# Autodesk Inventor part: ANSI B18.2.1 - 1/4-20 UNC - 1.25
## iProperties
Comments: To add or edit properties for Autodesk Inventor files, use iProperties.
Created: 2004-12
Part Number: ANSI B18.2.1 - 1/4-20 UNC - 1.25
Vendor: Autodesk Inc.
Document SubType Name: Modeling
Designer: John Blackburn
Material: Default
Description: Hex Cap Screw
Standard: ANSI B18.2.1
Alert: To add or edit properties for Autodesk Inventor files, use iProperties.
Control State: 0
Master: False
Checked Out: False
Shininess: 64.0
Length Units: 11272
Angle Units: 11279
Time Units: 11290
Mass Units: 11286
Length Display Precision: 3
Angle Display Precision: 2
Compacted: True
EGR: 3
Classification: un/spsc 31161513
Density: 0.0
Volumn: 0.0
Area: 0.0
PropertySet Name: Model Information
Author: John Blackburn
Revision Number: 8
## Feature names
1. Body [Revolution]
2. Head [Extrusion]
3. Chamfer1 [Revolution]
4. Chamfer2
